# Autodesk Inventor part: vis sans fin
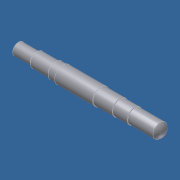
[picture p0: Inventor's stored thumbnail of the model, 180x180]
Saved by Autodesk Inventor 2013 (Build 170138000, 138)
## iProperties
Created: 2011-07
Part Number: vis sans fin
Document SubType Name: Modeling
Designer: Laur
Density: 7.85 g/cm^3
Material: Acier allié
Mass: 1.75606 g
Surface Area: 3.03993 cm^2
Volume: 0.223702 cm^3
Author: Laur
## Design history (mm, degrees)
sketch "image mobile vis"
  geometry: L1 (-30.561, 96.927)-(175.518, 96.927); L2 (175.518, 96.927)-(175.518, -73.484); L3 (175.518, -73.484)-(-30.561, -73.484); L4 (-30.561, -73.484)-(-30.561, 96.927); L5 (64.591, 42.179)-(62.495, 60.945); L6 (35.199, 50.078)-(35.199, 34.015); L7 (156.015, 56.182)-(156.015, 29); L8 (35.199, 42.046)-(156.015, 42.591); L9 (64.591, 42.179)-(64.493, 63.923); L10 (71.762, 58.186)-(71.902, 27.186); L11 (52.872, 58.228)-(78.277, 58.343); L12 (-6.193, -32.649)-(101.793, -35.599); L13 (-102.452, 17.647)-(-42.061, 17.647); L14 (-42.061, 17.647)-(-42.061, -18.434); L15 (-42.061, -18.434)-(-102.452, -18.434); L16 (-102.452, -18.434)-(-102.452, 17.647); L17 (-22.06, 49.224)-(0.933, 49.224); L18 (-22.598, 35.832)-(-1.695, 35.832); L19 (15.715, 48.763)-(20.372, 48.763); L20 (0.395, 42.302)-(-13.701, 42.302); C1 r 9.18 at (0.395, 42.302); 1 further point; 1 other entity
  constraints: 24 end point, 5 parallel, 4 perpendicular, 2 midpoint, 1 centre point, 1 point on line, 4 other
  dimensions: "d31" = 16.06298 distance of L6.start L6.end; "d32" = 27.18177 distance of L7.start L7.end; "d34" = 34.015 vertical distance of point (0, 0) L6.end; "d35" = 35.19926 horizontal distance of point (0, 0) L6.end (derived); "d46" = 83.8857 deg angle of L8 L5 (derived); "d47" = 31 vertical distance of L10.start L10.end; "d49" = 25.40515 horizontal distance of L11.start L11.end; "d73" = 18.36 diameter of C1; "d80" = 108.02652 distance of L12.start L12.end; "d92" = 13.392 distance between parallel lines of L18 L17
  node "Image1"
sketch "Esquisse formes générales"
  geometry: L1 (0, 0)-(31.247, 0); L2 (0.537, 1.24)-(4.237, 1.24); L3 (4.237, 1.24)-(4.487, 1.49); L4 (4.487, 1.49)-(8.237, 1.49); L5 (8.237, 1.49)-(8.397, 1.65); L6 (8.397, 1.65)-(9.897, 1.65); L7 (9.897, 1.65)-(9.897, 1.75); L8 (9.897, 1.75)-(17.897, 1.75); L9 (17.897, 1.75)-(17.897, 1.65); L10 (17.897, 1.65)-(21.897, 1.65); L11 (25.047, 1.5)-(30.347, 1.5); L12 (21.97, 1.578)-(24.97, 1.578); L13 (24.97, 1.578)-(25.047, 1.5); L14 (21.897, 1.65)-(21.97, 1.578); A1 r 1.7 centre (1.7, 0) between (0.537, 1.24) and (0, 0); A2 r 1.7 centre (29.547, 0) between (31.247, 0) and (30.347, 1.5)
  constraints: 28 end point, 8 parallel, 5 point on circle, 3 perpendicular, 3 point on line, 2 centre point, 1 horizontal
  dimensions: "d127" = 2.48 diameter of L2 L1; "d129" = 1.7 radius of A1; "d131" = 2.98 diameter of L4 L1; "d132" = 45 deg angle of L4 L3; "d133" = 3.7 distance of L2.start L2.end; "d134" = 1.5 distance of L5.end L6.end; "d135" = 8 distance of L7.end L8.end; "d136" = 3.3 diameter of L6 L1; "d137" = 3.5 diameter of L8 L1; "d138" = 3.75 distance of L3.end L4.end; "d139" = 4 distance of L9.end L10.end; "d140" = 3.3 diameter of L10 L1 (derived); "d141" = 3 diameter of L11 L1; "d142" = 1.7 radius of A2 (derived); "d145" = 3.155 diameter of L12 L1; "d146" = 3 distance of L12.start L12.end; "d147" = 5.3 distance of L11.start L11.end
revolve "Formes arbre" sketch "Esquisse formes générales" stored, may be unused: angle "d144" = 90 deg
node "Solide1"
node "Corps solides"
node "Corps surfaciques"
